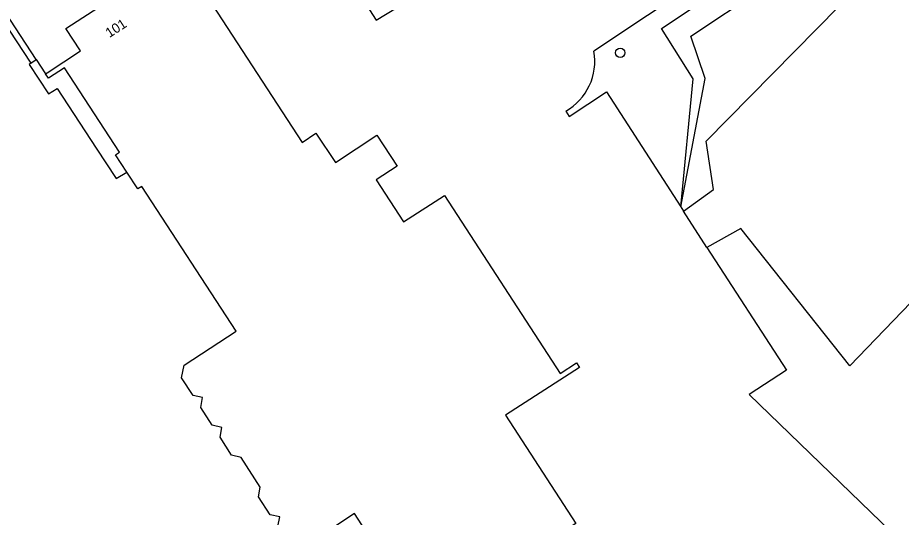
# Model space of a CAD drawing. Extents: x 156061 to 157804, y 383451 to 385640.
# Drawn here: x 156329.1 to 156419.9, y 385394.5 to 385445.9 of the extents above; entities that cross this region are included whole.
import ezdxf

# ---------------------------------------------------------------- set-up
doc = ezdxf.new("R2010")
doc.units = 0
for name, color, linetype in [('IMGEO_Boom', 7, 'Continuous'), ('IMGEO_Groenvoorziening', 7, 'Continuous'), ('IMGEO_Pand', 7, 'Continuous'), ('IMGEO_Pand_nummerreeks', 7, 'Continuous'), ('IMGEO_Parkeervlak_gesloten', 7, 'Continuous'), ('IMGEO_Parkeervlak_open', 7, 'Continuous'), ('IMGEO_Rijbaan_lokaal_open', 7, 'Continuous'), ('IMGEO_Voetpad_open', 7, 'Continuous')]:
    doc.layers.add(name, color=color, linetype=linetype)

msp = doc.modelspace()

# ---------------------------------------------------------------- linework, layer by layer
at = {"layer": 'IMGEO_Boom'}
msp.add_circle((156390.986, 385442.258), 0.489, dxfattribs=at)
at = {"layer": 'IMGEO_Groenvoorziening'}
for points in [[(156316.945, 385461.751), (156317.186, 385461.382), (156330.427, 385441.19)], [(156397.204, 385426.419), (156398.475, 385439.57), (156395.211, 385444.751), (156406.965, 385452.587)], [(156397.204, 385426.419), (156399.697, 385439.623), (156398.226, 385443.957), (156405.46, 385448.805)]]:
    msp.add_lwpolyline(points, dxfattribs=at)
at = {"layer": 'IMGEO_Pand'}
for points in [[(156331.943, 385440.092), (156332.089, 385440.188), (156335.512, 385442.442), (156334.01, 385444.763), (156341.394, 385449.556), (156342.901, 385447.245), (156348.922, 385451.157)], [(156348.922, 385451.157), (156349.216, 385450.712), (156347.517, 385449.635), (156358.292, 385433.036), (156359.724, 385434.004), (156361.723, 385430.995), (156365.984, 385433.784), (156368.074, 385430.595), (156365.924, 385429.194), (156368.728, 385424.868), (156372.927, 385427.602), (156384.822, 385409.281), (156386.502, 385410.389), (156386.784, 385409.921), (156379.186, 385405.001), (156386.42, 385393.874), (156377.098, 385387.813), (156378.788, 385385.214), (156372.584, 385381.181)], [(156340.295, 385429.992), (156339.136, 385431.768), (156339.546, 385432.036), (156333.882, 385440.727), (156332.234, 385439.642), (156331.943, 385440.092)], [(156355.82, 385393.562), (156356.022, 385394.557), (156355.033, 385394.772), (156353.823, 385396.63), (156353.989, 385397.606), (156352.025, 385400.672), (156351.045, 385400.895), (156349.869, 385402.745), (156350.054, 385403.756), (156349.046, 385403.966), (156347.901, 385405.803), (156348.073, 385406.814), (156347.107, 385407.022), (156345.899, 385408.863), (156346.171, 385410.141), (156351.509, 385413.653), (156341.841, 385428.524), (156341.425, 385428.262), (156340.295, 385429.992)], [(156369.348, 385386.163), (156363.674, 385394.896), (156358.376, 385391.39)]]:
    msp.add_lwpolyline(points, dxfattribs=at)
at = {"layer": 'IMGEO_Parkeervlak_gesloten'}
msp.add_lwpolyline([(156397.478, 385425.995), (156400.569, 385428.192), (156399.824, 385433.174), (156424.804, 385458.586), (156443.222, 385439.818), (156414.582, 385410.086), (156403.394, 385424.192), (156399.901, 385422.244)], dxfattribs=at)
at = {"layer": 'IMGEO_Parkeervlak_open'}
msp.add_lwpolyline([(156330.985, 385441.559), (156317.547, 385462.129)], dxfattribs=at)
at = {"layer": 'IMGEO_Rijbaan_lokaal_open'}
for points in [[(156358.192, 385457.177), (156358.242, 385457.212), (156358.438, 385457.213), (156365.921, 385445.613), (156379.577, 385453.937)], [(156406.811, 385454.601), (156400.403, 385450.517), (156399.309, 385449.786), (156388.285, 385442.417)], [(156385.394, 385436.246), (156385.722, 385435.723), (156389.572, 385438.23), (156397.204, 385426.419)], [(156397.204, 385426.419), (156397.478, 385425.995)], [(156399.901, 385422.244), (156397.478, 385425.995)], [(156399.901, 385422.244), (156408.058, 385409.621), (156404.25, 385407.149), (156419.86, 385392.019), (156388.044, 385359.282), (156384.467, 385362.717), (156383.724, 385361.973), (156379.209, 385366.204), (156379.953, 385366.895), (156376.305, 385370.436), (156378.254, 385372.46), (156372.584, 385381.181)]]:
    msp.add_lwpolyline(points, dxfattribs=at)
msp.add_arc((156382.415, 385441.404), 5.957, 300.00714, 9.78841, dxfattribs=at)
at = {"layer": 'IMGEO_Voetpad_open'}
for points in [[(156330.427, 385441.19), (156330.247, 385441.071), (156332.253, 385438.03), (156333.122, 385438.573), (156337.146, 385432.464), (156339.21, 385429.331), (156340.295, 385429.992)], [(156330.427, 385441.19), (156330.985, 385441.559)], [(156330.985, 385441.559), (156331.943, 385440.092)]]:
    msp.add_lwpolyline(points, dxfattribs=at)

# ---------------------------------------------------------------- texts
at = {"layer": 'IMGEO_Pand_nummerreeks'}
msp.add_text('101', height=1, rotation=32.98785, dxfattribs=at).set_placement((156338.504, 385443.77))

doc.saveas('drawing.dxf')
